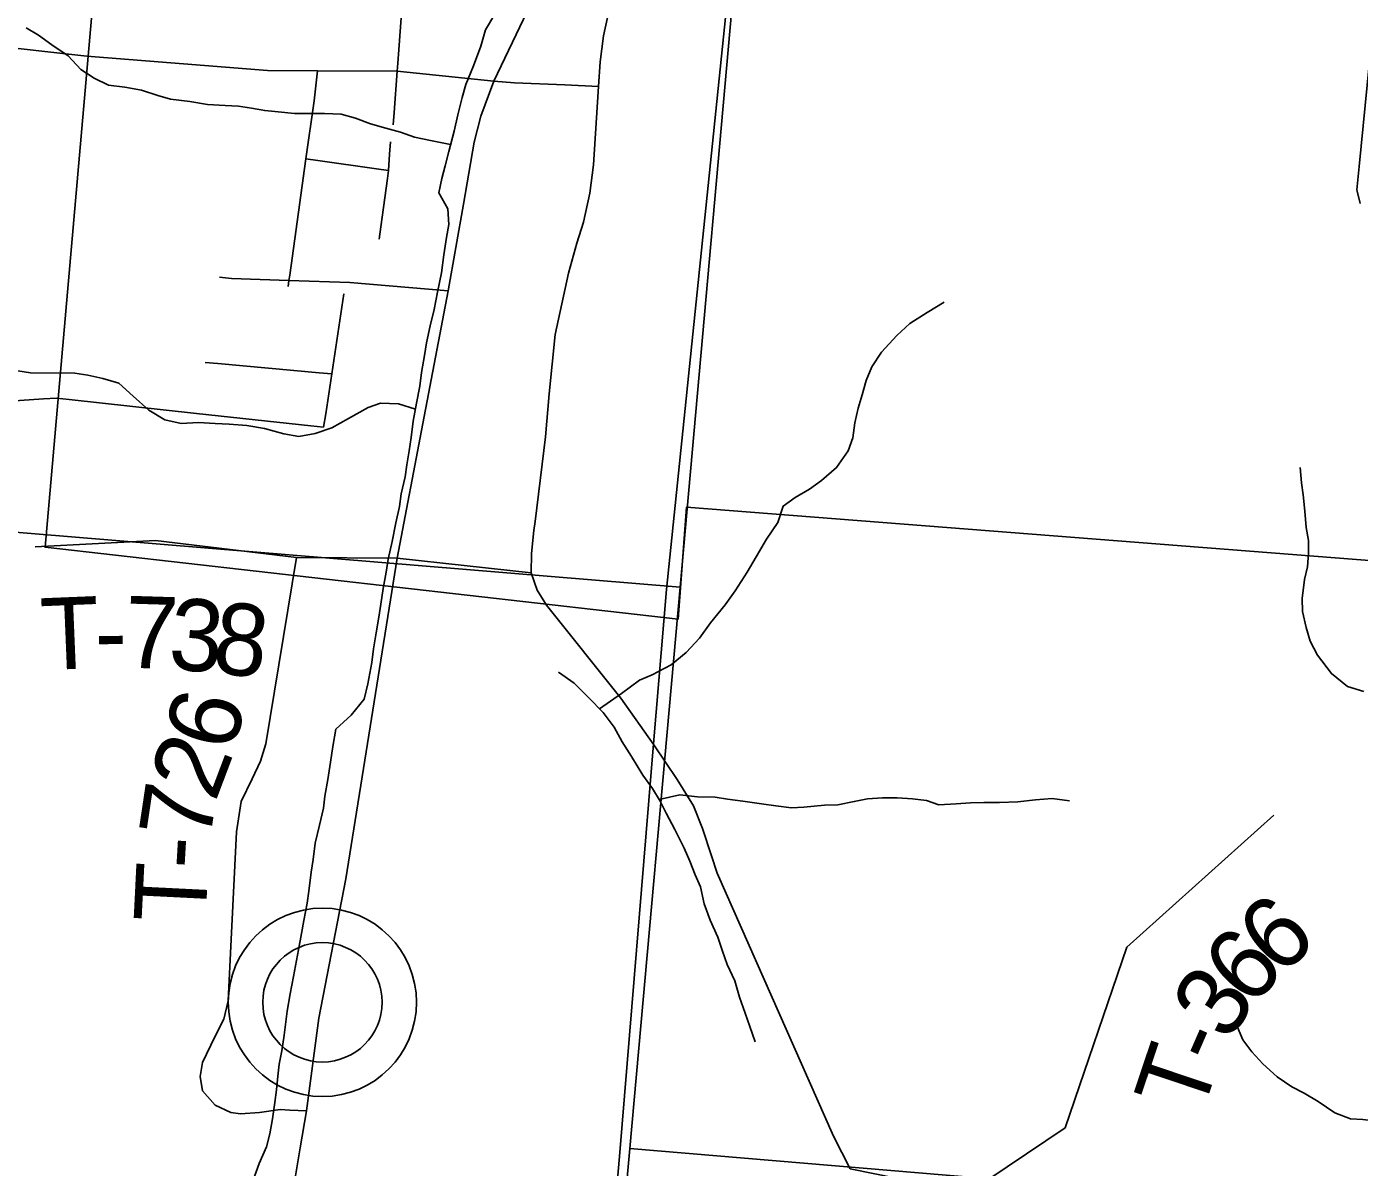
# Model space of a CAD drawing. Extents: x 0 to 42, y 0 to 22.
# Drawn here: x 4.628 to 5.155, y 14.736 to 15.186 of the extents above; entities that cross this region are included whole.
import ezdxf

# ---------------------------------------------------------------- set-up
doc = ezdxf.new("R2010")
doc.units = 0
for name, color, linetype in [('GM_X_City_Street', 7, 'Continuous'), ('GM_X_Corporation', 7, 'Continuous'), ('GM_X_County_Road', 7, 'Continuous'), ('GM_X_Minor_River', 7, 'Continuous'), ('GM_X_Section', 7, 'Continuous'), ('GM_X_State_Route', 7, 'Continuous'), ('GM_X_Township_Road', 7, 'Continuous'), ('GM_X_Township_Road_Text', 7, 'Continuous'), ('GM_X_Unincorporated', 7, 'Continuous'), ('GM_X_Unincorporated_Location', 7, 'Continuous')]:
    doc.layers.add(name, color=color, linetype=linetype)

msp = doc.modelspace()

# ---------------------------------------------------------------- linework, layer by layer
at = {"layer": 'GM_X_City_Street'}
for points in [[(5.15497, 15.11653), (5.15376, 15.12135), (5.15362, 15.12189), (5.15454, 15.1312), (5.16092, 15.1954), (5.16102, 15.19645), (5.16098, 15.20531), (5.16087, 15.23154), (5.16081, 15.24708), (5.1635, 15.29034), (5.16048, 15.32935), (5.16045, 15.33398), (5.1579, 15.33861), (5.15264, 15.34821), (5.13881, 15.37341), (5.13712, 15.37647), (5.13478, 15.38245), (5.1234, 15.41149), (5.09497, 15.48408), (5.09313, 15.48877)], [(4.77285, 15.14763), (4.77322, 15.15251), (4.77444, 15.16878), (4.77469, 15.17203), (4.77616, 15.19154), (4.77645, 15.19544), (4.77654, 15.19653), (4.77695, 15.20129), (4.78212, 15.22866), (4.7829, 15.24021), (4.78496, 15.25941), (4.78981, 15.30813), (4.79012, 15.31123), (4.7889, 15.33285), (4.78934, 15.33772)], [(4.73131, 15.08369), (4.73165, 15.08615), (4.73195, 15.08828), (4.73837, 15.13418), (4.74158, 15.15712), (4.74297, 15.169)], [(4.81258, 15.16486), (4.82075, 15.16416), (4.84068, 15.16345), (4.85391, 15.1628)], [(4.76735, 15.10248), (4.76798, 15.10727), (4.77053, 15.12642), (4.77095, 15.12961), (4.7714, 15.13603), (4.77173, 15.14086)], [(4.73837, 15.13418), (4.74302, 15.13352), (4.76629, 15.13026), (4.77095, 15.12961)], [(4.7042, 15.08749), (4.70897, 15.08686), (4.73165, 15.08615), (4.75565, 15.08539), (4.79458, 15.08197)], [(4.74535, 15.02811), (4.74615, 15.03339), (4.74855, 15.04922), (4.75255, 15.07561), (4.75335, 15.08089)], [(4.69851, 15.05372), (4.70351, 15.05327), (4.74355, 15.04967), (4.74855, 15.04922)], [(4.63972, 15.03968), (4.64475, 15.03913), (4.69505, 15.03363), (4.74032, 15.02868), (4.74535, 15.02811)]]:
    msp.add_lwpolyline(points, dxfattribs=at)
at = {"layer": 'GM_X_Corporation'}
msp.add_lwpolyline([(5.16196, 14.97517), (4.88876, 14.99658), (4.88543, 14.95236), (4.63528, 14.98072), (4.68008, 15.49207), (4.93011, 15.46404), (4.93307, 15.50398), (4.93794, 15.56054), (4.96217, 15.55961), (4.96779, 15.62081), (4.94292, 15.61852), (4.95512, 15.75908), (4.99562, 15.75482), (5.00021, 15.7388), (4.97496, 15.55913), (4.96874, 15.50211), (4.98148, 15.50141), (4.98529, 15.56421), (5.0572, 15.55859), (5.07049, 15.52131), (5.05299, 15.52203), (5.06731, 15.49078), (5.20978, 15.47989)], dxfattribs=at)
at = {"layer": 'GM_X_County_Road'}
msp.add_lwpolyline([(4.53585, 15.03258), (4.63469, 15.03934), (4.63972, 15.03968)], dxfattribs=at)
at = {"layer": 'GM_X_Minor_River'}
for points in [[(4.79688, 15.14518), (4.79842, 15.15162), (4.80015, 15.15843), (4.8015, 15.16355), (4.80455, 15.17092), (4.80742, 15.17868), (4.80934, 15.18512), (4.81295, 15.19136)], [(4.79549, 15.13984), (4.78761, 15.14143), (4.78119, 15.14279), (4.77571, 15.14471), (4.76986, 15.14625), (4.76382, 15.14798), (4.75798, 15.15028), (4.75232, 15.15182), (4.7457, 15.15204), (4.7338, 15.1521), (4.72738, 15.15269), (4.72209, 15.15328), (4.7168, 15.15426), (4.7117, 15.15504), (4.70641, 15.15525), (4.69942, 15.15566), (4.69244, 15.15683), (4.68488, 15.15781), (4.67978, 15.15916), (4.67337, 15.16127), (4.66676, 15.16244), (4.66034, 15.16323), (4.65468, 15.1661), (4.64941, 15.16953), (4.64433, 15.17486), (4.63792, 15.17925), (4.63265, 15.18306), (4.62775, 15.18593)], [(4.71743, 14.73064), (4.71991, 14.73726), (4.72278, 14.74388), (4.72412, 14.74899), (4.72509, 14.75486), (4.72606, 14.7613), (4.72665, 14.76642), (4.72724, 14.77172), (4.72783, 14.77646), (4.7288, 14.78176), (4.72977, 14.78801), (4.73094, 14.79748), (4.73211, 14.8043), (4.73346, 14.81112), (4.7354, 14.82172), (4.73656, 14.82816), (4.73752, 14.83328), (4.73888, 14.84009), (4.73946, 14.84483), (4.74044, 14.85241), (4.74122, 14.85733), (4.742, 14.86377), (4.74373, 14.87097), (4.74527, 14.87759), (4.74586, 14.88233), (4.74702, 14.88896), (4.748, 14.89578), (4.74897, 14.90203), (4.75013, 14.90885), (4.7562, 14.91432), (4.76133, 14.92074), (4.76287, 14.92679), (4.76442, 14.93513), (4.76501, 14.94062), (4.76617, 14.94687), (4.76714, 14.95312), (4.76792, 14.95824), (4.76889, 14.96449), (4.77005, 14.97092), (4.77083, 14.97604), (4.77237, 14.98305), (4.77392, 14.99043), (4.77527, 14.99687), (4.77604, 15.00179), (4.77759, 15.00861), (4.77817, 15.01335), (4.77914, 15.01884), (4.77992, 15.02414), (4.7807, 15.03058), (4.78206, 15.03759), (4.78341, 15.04441), (4.784, 15.04971), (4.78516, 15.05653), (4.78594, 15.06145), (4.78748, 15.06827), (4.78902, 15.07471), (4.79037, 15.08152), (4.79192, 15.0891), (4.79289, 15.0963), (4.79387, 15.10312), (4.79483, 15.10823), (4.79448, 15.11449), (4.79092, 15.12076), (4.79208, 15.12644), (4.79342, 15.13136), (4.79477, 15.13704), (4.79688, 15.14518)], [(4.85437, 14.91688), (4.863, 14.92294), (4.8702, 14.92822), (4.87513, 14.93028), (4.8827, 14.93423), (4.88858, 14.93913), (4.89389, 14.94479), (4.89827, 14.95084), (4.90397, 14.95801), (4.90796, 14.96349), (4.91271, 14.97087), (4.91633, 14.97692), (4.92033, 14.98391), (4.92489, 14.99053), (4.927, 14.99696), (4.93174, 15.00035), (4.93742, 15.00374), (4.94216, 15.00713), (4.94804, 15.01222), (4.9526, 15.01883), (4.95451, 15.02394), (4.95529, 15.02982), (4.95664, 15.03569), (4.95818, 15.04099), (4.95971, 15.04667), (4.962, 15.05196), (4.96581, 15.05782), (4.97188, 15.06443), (4.977, 15.06915), (4.98382, 15.07348), (4.99064, 15.07762)], [(4.78161, 15.03528), (4.77487, 15.03743), (4.76788, 15.03765), (4.76296, 15.03597), (4.7552, 15.03164), (4.74857, 15.02788), (4.74194, 15.02564), (4.73552, 15.02453), (4.72966, 15.0255), (4.72192, 15.02762), (4.71494, 15.02879), (4.70795, 15.02939), (4.70247, 15.0296), (4.69586, 15.03001), (4.68905, 15.02966), (4.68263, 15.03102), (4.67623, 15.03484), (4.67001, 15.04036), (4.66437, 15.04551), (4.65814, 15.04743), (4.6521, 15.04878), (4.647, 15.04956), (4.62943, 15.04964), (4.62452, 15.05042)], [(5.15644, 14.92376), (5.15002, 14.92568), (5.14362, 14.93083), (5.13817, 14.93805), (5.13517, 14.94356), (5.13369, 14.94907), (5.1322, 14.95533), (5.13203, 14.96044), (5.13301, 14.96802), (5.13417, 14.97294), (5.13457, 14.97844), (5.13459, 14.98337), (5.13367, 14.98849), (5.13313, 14.99493), (5.1324, 15.00138), (5.13185, 15.00612), (5.13131, 15.01219)], [(4.8381, 14.93139), (4.84431, 14.927), (4.85015, 14.92129), (4.85579, 14.91539), (4.86011, 14.90969), (4.8633, 14.9038), (4.86705, 14.89809), (4.87155, 14.89068), (4.87531, 14.88536), (4.87831, 14.88042), (4.88075, 14.87567), (4.88412, 14.86921), (4.88787, 14.8618), (4.89011, 14.85667), (4.89217, 14.85136), (4.89423, 14.84661), (4.89571, 14.83978), (4.89814, 14.83333), (4.90113, 14.82668), (4.903, 14.82117), (4.90486, 14.81586), (4.90786, 14.8094), (4.90972, 14.80295), (4.91196, 14.79668), (4.91383, 14.79137), (4.91588, 14.7853)], [(4.87792, 14.88106), (4.88607, 14.88285), (4.89306, 14.88206), (4.90005, 14.88203), (4.90496, 14.88125), (4.911, 14.88046), (4.91837, 14.8793), (4.92403, 14.87851), (4.93026, 14.87773), (4.93518, 14.87808), (4.9433, 14.87881), (4.9486, 14.87897), (4.95503, 14.88027), (4.96032, 14.88139), (4.96618, 14.88174), (4.97204, 14.88172), (4.97808, 14.88131), (4.98356, 14.88072), (4.98846, 14.87899), (4.99527, 14.87934), (5.00094, 14.8797), (5.00623, 14.87986), (5.01246, 14.87983), (5.01964, 14.88018), (5.02664, 14.88091), (5.03325, 14.88145), (5.04005, 14.88048)], [(5.19453, 14.73122), (5.18794, 14.73712), (5.18192, 14.74359), (5.17495, 14.74893), (5.16855, 14.75237), (5.16251, 14.75391), (5.15608, 14.75469), (5.15117, 14.75491), (5.14495, 14.75721), (5.13835, 14.76178), (5.13289, 14.76503), (5.12799, 14.76751), (5.12215, 14.77152), (5.1165, 14.77666), (5.11218, 14.78142), (5.10861, 14.78617), (5.10655, 14.79111)]]:
    msp.add_lwpolyline(points, dxfattribs=at)
at = {"layer": 'GM_X_Section'}
for points in [[(4.43443, 15.52355), (4.93086, 15.46885), (4.91139, 15.24667), (4.8862, 14.96502), (4.39069, 15.00589)], [(4.91139, 15.24667), (5.46922, 15.20689), (5.42587, 14.69605), (4.86634, 14.74322), (4.8862, 14.96502)], [(4.39069, 15.00589), (4.8862, 14.96502), (4.86634, 14.74322), (4.83953, 14.44809), (4.34454, 14.49165)], [(4.86634, 14.74322), (5.42587, 14.69605), (5.38206, 14.19771), (4.82178, 14.24637), (4.83953, 14.44809)]]:
    msp.add_lwpolyline(points, close=True, dxfattribs=at)
at = {"layer": 'GM_X_State_Route'}
for p, q in [((4.81258, 15.16486), (4.82584, 15.19241)), ((4.77434, 14.9764), (4.78456, 15.02967))]:
    msp.add_line(p, q, dxfattribs=at)
for points in [[(4.25539, 15.16112), (4.25763, 15.16198), (4.27861, 15.17507), (4.2916, 15.18558), (4.32492, 15.23484), (4.32986, 15.24216), (4.3478, 15.26112), (4.36483, 15.26944), (4.38104, 15.27151), (4.41469, 15.26403), (4.44129, 15.25613), (4.49073, 15.23326), (4.50518, 15.2259), (4.53478, 15.21082), (4.58049, 15.18587), (4.59897, 15.18057), (4.61143, 15.1792), (4.65174, 15.17475)], [(4.87179, 15.22026), (4.86345, 15.20447), (4.85747, 15.19007), (4.856, 15.18276), (4.85457, 15.17256), (4.85391, 15.1628), (4.85194, 15.13176), (4.85051, 15.12058), (4.8481, 15.10917), (4.84547, 15.10084), (4.84218, 15.08899), (4.83685, 15.06481), (4.83442, 15.04136), (4.83308, 15.02429), (4.82891, 14.99087)], [(4.65174, 15.17475), (4.72321, 15.16914), (4.74297, 15.169), (4.77444, 15.16878), (4.81258, 15.16486)], [(4.78456, 15.02967), (4.79458, 15.08197), (4.80062, 15.1163), (4.80478, 15.14075), (4.80753, 15.15106), (4.81258, 15.16486)], [(4.82891, 14.99087), (4.82847, 14.98732), (4.82747, 14.97823), (4.82737, 14.97066)], [(4.73608, 14.74338), (4.73854, 14.75803), (4.74345, 14.79462), (4.75413, 14.84977), (4.77434, 14.9764)], [(4.82737, 14.97066), (4.82979, 14.96376), (4.83342, 14.95781), (4.86281, 14.92113), (4.87587, 14.90273), (4.88506, 14.88896), (4.89156, 14.87858), (4.89504, 14.86966), (4.89866, 14.85881), (4.90085, 14.85201), (4.9468, 14.74805), (4.95349, 14.73511)], [(4.45857, 14.54977), (4.48467, 14.56201), (4.52086, 14.5751), (4.54702, 14.58338), (4.6237, 14.60399), (4.6428, 14.60969), (4.65619, 14.61582), (4.66902, 14.62309), (4.68085, 14.63193), (4.69446, 14.64428), (4.70408, 14.65648), (4.71426, 14.6714), (4.72244, 14.68934), (4.7266, 14.69997), (4.73198, 14.71897), (4.73608, 14.74338)]]:
    msp.add_lwpolyline(points, dxfattribs=at)
at = {"layer": 'GM_X_Township_Road'}
for points in [[(2.1, 16.7767), (2.1, 14.1), (4.80642, 14.1), (4.86241, 14.74155), (4.87577, 14.903), (4.88082, 14.9641), (4.90774, 15.22465), (4.90782, 15.22542), (4.91025, 15.24876), (4.91234, 15.26666), (4.91693, 15.30071), (4.92061, 15.33827), (4.92229, 15.35537), (4.9225, 15.35759), (4.92364, 15.36537), (4.92223, 15.37611), (4.92602, 15.41635), (4.9302, 15.46506), (4.93268, 15.49943), (4.95383, 15.74551), (4.96357, 15.8483), (4.97611, 15.98164)], [(4.97611, 15.98164), (4.96357, 15.8483), (4.95383, 15.74551), (4.93268, 15.49943), (4.9302, 15.46506), (4.92602, 15.41635), (4.92223, 15.37611), (4.92364, 15.36537), (4.9225, 15.35759), (4.92229, 15.35537), (4.92061, 15.33827), (4.91693, 15.30071), (4.91234, 15.26666), (4.91025, 15.24876), (4.90782, 15.22542), (4.90774, 15.22465), (4.88082, 14.9641), (4.87577, 14.903), (4.86241, 14.74155), (4.80642, 14.1), (8.05023, 14.1)], [(4.63135, 14.98092), (4.67885, 14.98344), (4.73027, 14.97727)], [(4.73854, 14.75803), (4.73198, 14.75833), (4.72811, 14.75862), (4.72006, 14.75743), (4.71246, 14.75684), (4.70873, 14.75743), (4.70251, 14.76036), (4.69742, 14.76598), (4.69654, 14.77161), (4.69742, 14.77722), (4.70233, 14.78724), (4.70584, 14.79426), (4.7076, 14.80146), (4.70883, 14.8257), (4.71091, 14.86824), (4.71269, 14.88033), (4.71713, 14.88922), (4.72033, 14.89616), (4.72247, 14.90309), (4.73465, 14.97674)], [(4.73027, 14.97727), (4.73465, 14.97674), (4.77434, 14.9764), (4.82737, 14.97066)], [(4.95349, 14.73511), (5.00023, 14.72572), (5.03842, 14.75135), (5.06278, 14.82275), (5.12083, 14.87494)]]:
    msp.add_lwpolyline(points, dxfattribs=at)
at = {"layer": 'GM_X_Unincorporated'}
for radius in [0.0372, 0.02358]:
    msp.add_circle((4.74485, 14.80093), radius, dxfattribs=at)
at = {"layer": 'GM_X_Unincorporated_Location'}
msp.add_line((4.74485, 14.80093), (4.74485, 14.80093), dxfattribs=at)

# ---------------------------------------------------------------- texts
at = {"layer": 'GM_X_Township_Road_Text'}
for s, rotation, p in [('T', 2.3449, (4.63405, 14.93214)), ('7', 358.2564, (4.66641, 14.93319)), ('3', 355.4105, (4.68353, 14.93268)), ('8', 353.596, (4.70073, 14.9313)), ('-', 0.8821, (4.65509, 14.933)), ('6', 75.7395, (4.70963, 14.89919)), ('2', 69.2838, (4.70244, 14.87963)), ('7', 81.513, (4.70028, 14.86401)), ('-', 86.654, (4.69967, 14.85313)), ('T', 87.1515, (4.69862, 14.83201)), ('6', 42.0202, (5.12309, 14.81067)), ('6', 46.9217, (5.1116, 14.79834)), ('3', 56.7248, (5.10279, 14.78472)), ('-', 66.5279, (5.09875, 14.77514)), ('T', 71.4294, (5.09221, 14.7556))]:
    msp.add_text(s, height=0.02841, rotation=rotation, dxfattribs=at).set_placement(p)

doc.saveas('drawing.dxf')
